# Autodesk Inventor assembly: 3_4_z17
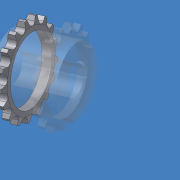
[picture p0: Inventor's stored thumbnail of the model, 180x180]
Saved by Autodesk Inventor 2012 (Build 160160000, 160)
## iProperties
Company: CAD-Verlag
Created: 2004-09
Part Number: 3_4_z17
Document SubType Name: Assembly
Designer: Greiling
Manufacturer: Standard
Standards Organization: Custom
Control State: 0
Master: False
Checked Out: False
Shininess: 64.0
Length Units: 11269
Angle Units: 11279
Time Units: 11290
Mass Units: 11283
Length Display Precision: 3
Angle Display Precision: 2
Compacted: True
Density: 0.0
Volumn: 0.0
Area: 0.0
PropertySet Name: Model Information
Author: Jürgen Kronas
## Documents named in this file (2)
- C:\DemoDaten2012\CAD Daten\Daten Vault 2012 Inventor\Kapitel 6\6.4\Rollenbahn\Rollenbahn 1400\3_4_z17.iam
- C:\DemoDaten2012\CAD Daten\Daten Vault 2012 Inventor\Kapitel 6\6.4\Rollenbahn\Rollenbahn 1400\N023311009N7GGB.ipt
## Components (1 placed, 1 different names)
1. Kettentyp 12 B:1
